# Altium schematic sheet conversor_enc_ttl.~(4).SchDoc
size A4
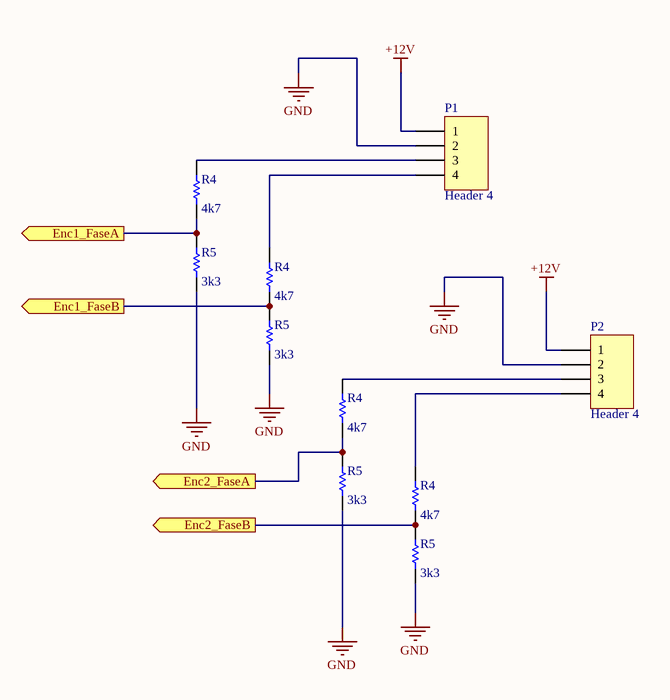
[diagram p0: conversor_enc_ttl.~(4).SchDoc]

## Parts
(Parts that share a designator on the sheet are numbered #1, #2 ... from top to bottom, then left to right.)
P1  Header 4  [HDR1X4]
P2  Header 4  [HDR1X4]
R4#1  value 4k7  [1005[0402]]  (hidden comment: metal film 2%)
R4#2  value 4k7  [1005[0402]]  (hidden comment: metal film 2%)
R4#3  value 4k7  [1005[0402]]  (hidden comment: metal film 2%)
R4#4  value 4k7  [1005[0402]]  (hidden comment: metal film 2%)
R5#1  value 3k3  [1005[0402]]  (hidden comment: metal film 2%)
R5#2  value 3k3  [1005[0402]]  (hidden comment: metal film 2%)
R5#3  value 3k3  [1005[0402]]  (hidden comment: metal film 2%)
R5#4  value 3k3  [1005[0402]]  (hidden comment: metal film 2%)

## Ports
Enc1_FaseA (out), Enc1_FaseB (out), Enc2_FaseA (out), Enc2_FaseB (out)

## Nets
+12V: P1.1 P2.1
GND: P1.2 P2.2 R5#1.1 R5#2.1 R5#3.1 R5#4.1
Enc1_FaseA: R4#1.1 R5#1.2 ; port Enc1_FaseA
Enc1_FaseB: R4#2.1 R5#2.2 ; port Enc1_FaseB
Enc2_FaseA: R4#3.1 R5#3.2 ; port Enc2_FaseA
Enc2_FaseB: R4#4.1 R5#4.2 ; port Enc2_FaseB
NetP1_3: P1.3 R4#1.2
NetP1_4: P1.4 R4#2.2
NetP2_3: P2.3 R4#3.2
NetP2_4: P2.4 R4#4.2

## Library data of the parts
P1 P2 = Header 4: Header, 4-Pin
R4#1-R4#4 R5#1-R5#4 = Res Semi: Semiconductor Resistor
